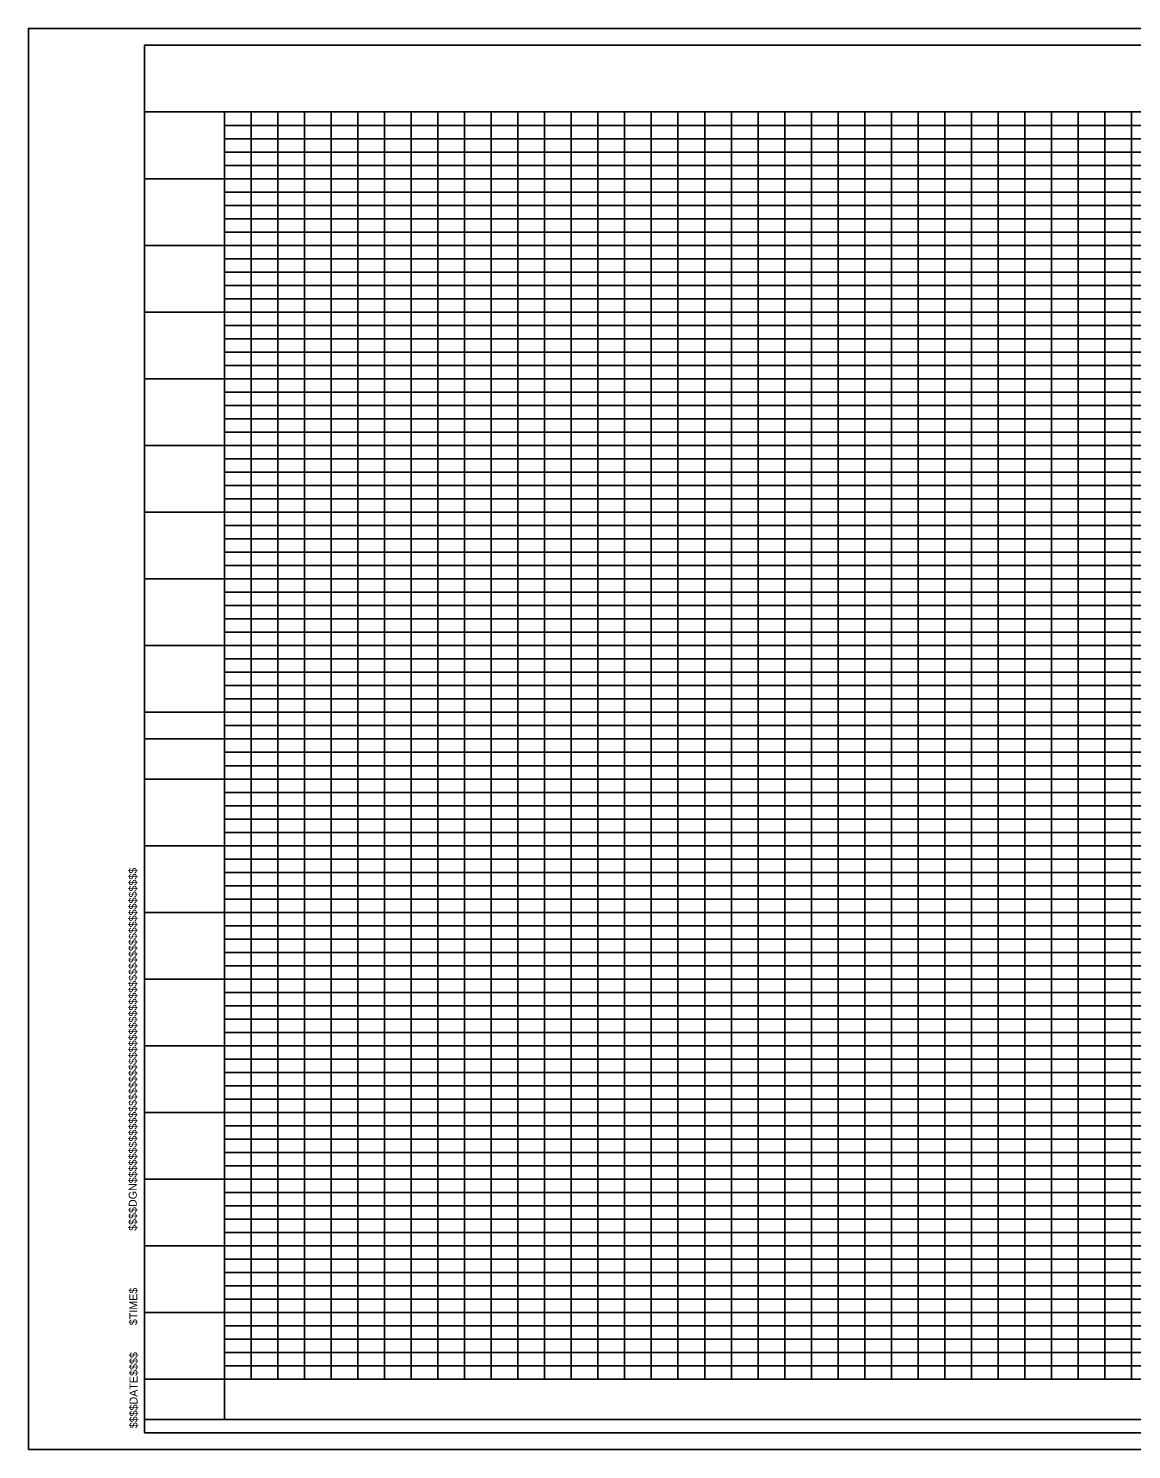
# Model space of a CAD drawing. Extents: x -87 to 2484, y -13 to 1056.
# Drawn here: x -87 to 740, y -13 to 1053 of the extents above; entities that cross this region are included whole.
import ezdxf

# ---------------------------------------------------------------- set-up
doc = ezdxf.new("R2010")
doc.units = 0
for name, color, linetype in [('D_CFL_Clip_Boundary_1', 7, 'Continuous'), ('D_CFL_Clip_Boundary_2', 7, 'Continuous'), ('D_CFL_Sheet_Border_ PlotShape', 7, 'Continuous'), ('D_CFL_Sheet_Border_Base', 7, 'Continuous'), ('D_CFL_Sheet_Border_Plan_Plan', 7, 'Continuous'), ('D_CFL_Sheet_Border_PnP', 7, 'Continuous'), ('D_CFL_Sheet_Border_Profile', 7, 'Continuous')]:
    doc.layers.add(name, color=color, linetype=linetype)

msp = doc.modelspace()

# ---------------------------------------------------------------- linework, layer by layer
at = {"layer": 'D_CFL_Clip_Boundary_1'}
msp.add_lwpolyline([(0, 520), (0, 1040), (1305, 1040), (1305, 1000), (1560, 1000), (1560, 520)], close=True, dxfattribs=at)
msp.add_lwpolyline([(0, 520), (0, 1040), (1305, 1040), (1305, 1000), (1560, 1000), (1560, 520)], close=True, dxfattribs=at)
at = {"layer": 'D_CFL_Clip_Boundary_2'}
msp.add_lwpolyline([(1500, 520), (60, 520), (60, 40), (1500, 40)], close=True, dxfattribs=at)
msp.add_lwpolyline([(1500, 520), (60, 520), (60, 40), (1500, 40)], close=True, dxfattribs=at)
at = {"layer": 'D_CFL_Sheet_Border_ PlotShape'}
msp.add_line((-86.9, -12.7), (-86.9, -12.7), dxfattribs=at)
msp.add_line((-86.9, -12.7), (-86.9, -12.7), dxfattribs=at)
msp.add_lwpolyline([(-86.9, -12.7), (1576.9, -12.7), (1576.9, 1052.6), (-86.9, 1052.6)], close=True, dxfattribs=at)
msp.add_lwpolyline([(-86.9, -12.7), (1576.9, -12.7), (1576.9, 1052.6), (-86.9, 1052.6)], close=True, dxfattribs=at)
at = {"layer": 'D_CFL_Sheet_Border_Base'}
msp.add_lwpolyline([(0, 0), (1560, 0), (1560, 1040), (0, 1040)], close=True, dxfattribs=at)
msp.add_lwpolyline([(0, 0), (1560, 0), (1560, 1040), (0, 1040)], close=True, dxfattribs=at)
at = {"layer": 'D_CFL_Sheet_Border_Plan_Plan'}
msp.add_line((0, 520), (1560, 520), dxfattribs=at)
msp.add_line((0, 520), (1560, 520), dxfattribs=at)
at = {"layer": 'D_CFL_Sheet_Border_PnP'}
for p, q in [((0, 520), (1560, 520)), ((0, 520), (1560, 520)), ((60, 520), (60, 10)), ((60, 520), (60, 10)), ((80, 40), (80, 520)), ((80, 40), (80, 520)), ((100, 40), (100, 520)), ((100, 40), (100, 520)), ((120, 40), (120, 520)), ((120, 40), (120, 520)), ((140, 40), (140, 520)), ((140, 40), (140, 520)), ((160, 40), (160, 520)), ((160, 40), (160, 520)), ((180, 40), (180, 520)), ((180, 40), (180, 520)), ((200, 39.7), (200, 519.7)), ((200, 39.7), (200, 519.7)), ((220, 39.7), (220, 519.7)), ((220, 39.7), (220, 519.7)), ((240, 39.7), (240, 519.7)), ((240, 39.7), (240, 519.7)), ((260, 39.7), (260, 519.7)), ((260, 39.7), (260, 519.7)), ((280, 40), (280, 520)), ((280, 40), (280, 520)), ((300, 39.7), (300, 519.7)), ((300, 39.7), (300, 519.7)), ((320, 39.7), (320, 519.7)), ((320, 39.7), (320, 519.7)), ((340, 39.7), (340, 519.7)), ((340, 39.7), (340, 519.7)), ((360, 39.7), (360, 519.7)), ((360, 39.7), (360, 519.7)), ((380, 40), (380, 520)), ((380, 40), (380, 520)), ((400, 39.7), (400, 519.7)), ((400, 39.7), (400, 519.7)), ((420, 39.7), (420, 519.7)), ((420, 39.7), (420, 519.7)), ((440, 39.7), (440, 519.7)), ((440, 39.7), (440, 519.7)), ((460, 39.7), (460, 519.7)), ((460, 39.7), (460, 519.7)), ((480, 40), (480, 520)), ((480, 40), (480, 520)), ((500, 39.7), (500, 519.7)), ((500, 39.7), (500, 519.7)), ((520, 39.7), (520, 519.7)), ((520, 39.7), (520, 519.7)), ((540, 39.7), (540, 519.7)), ((540, 39.7), (540, 519.7)), ((560, 39.7), (560, 519.7)), ((560, 39.7), (560, 519.7)), ((580, 40), (580, 520)), ((580, 40), (580, 520)), ((600, 39.7), (600, 519.7)), ((600, 39.7), (600, 519.7)), ((620, 39.7), (620, 519.7)), ((620, 39.7), (620, 519.7)), ((640, 39.7), (640, 519.7)), ((640, 39.7), (640, 519.7)), ((660, 39.7), (660, 519.7)), ((660, 39.7), (660, 519.7)), ((680, 40), (680, 520)), ((680, 40), (680, 520)), ((700, 39.7), (700, 519.7)), ((700, 39.7), (700, 519.7)), ((720, 39.7), (720, 519.7)), ((720, 39.7), (720, 519.7)), ((60, 510), (1500, 510)), ((60, 510), (1500, 510)), ((60, 500), (1500, 500)), ((60, 500), (1500, 500)), ((60, 490), (0, 490)), ((60, 490), (0, 490)), ((60, 490), (1500, 490)), ((60, 490), (1500, 490)), ((60, 480), (1500, 480)), ((60, 480), (1500, 480)), ((60, 470), (1500, 470)), ((60, 470), (1500, 470)), ((60, 460), (1500, 460)), ((60, 460), (1500, 460)), ((60, 450), (1500, 450)), ((60, 450), (1500, 450)), ((60, 440), (0, 440)), ((60, 440), (0, 440)), ((60, 440), (1500, 440)), ((60, 440), (1500, 440)), ((60, 430), (1500, 430)), ((60, 430), (1500, 430)), ((60, 420), (1500, 420)), ((60, 420), (1500, 420)), ((60, 410), (1500, 410)), ((60, 410), (1500, 410)), ((60, 400), (1500, 400)), ((60, 400), (1500, 400)), ((60, 390), (0, 390)), ((60, 390), (0, 390)), ((60, 390), (1500, 390)), ((60, 390), (1500, 390)), ((60, 380), (1500, 380)), ((60, 380), (1500, 380)), ((60, 370), (1500, 370)), ((60, 370), (1500, 370)), ((60, 360), (1500, 360)), ((60, 360), (1500, 360)), ((60, 350), (1500, 350)), ((60, 350), (1500, 350)), ((60, 340), (0, 340)), ((60, 340), (0, 340)), ((60, 340), (1500, 340)), ((60, 340), (1500, 340)), ((60, 330), (1500, 330)), ((60, 330), (1500, 330)), ((60, 320), (1500, 320)), ((60, 320), (1500, 320)), ((60, 310), (1500, 310)), ((60, 310), (1500, 310)), ((60, 300), (1500, 300)), ((60, 300), (1500, 300)), ((60, 290), (0, 290)), ((60, 290), (0, 290)), ((60, 290), (1500, 290)), ((60, 290), (1500, 290)), ((60, 280), (1500, 280)), ((60, 280), (1500, 280)), ((60, 270), (1500, 270)), ((60, 270), (1500, 270)), ((60, 260), (1500, 260)), ((60, 260), (1500, 260)), ((60, 250), (1500, 250)), ((60, 250), (1500, 250)), ((60, 240), (0, 240)), ((60, 240), (0, 240)), ((60, 240), (1500, 240)), ((60, 240), (1500, 240)), ((60, 230), (1500, 230)), ((60, 230), (1500, 230)), ((60, 220), (1500, 220)), ((60, 220), (1500, 220)), ((60, 210), (1500, 210)), ((60, 210), (1500, 210)), ((60, 200), (1500, 200)), ((60, 200), (1500, 200)), ((60, 190), (0, 190)), ((60, 190), (0, 190)), ((60, 190), (1500, 190)), ((60, 190), (1500, 190)), ((60, 180), (1500, 180)), ((60, 180), (1500, 180)), ((60, 170), (1500, 170)), ((60, 170), (1500, 170)), ((60, 160), (1500, 160)), ((60, 160), (1500, 160)), ((60, 150), (1500, 150)), ((60, 150), (1500, 150)), ((60, 140), (0, 140)), ((60, 140), (0, 140)), ((60, 140), (1500, 140)), ((60, 140), (1500, 140)), ((60, 130), (1500, 130)), ((60, 130), (1500, 130)), ((60, 120), (1500, 120)), ((60, 120), (1500, 120)), ((60, 110), (1500, 110)), ((60, 110), (1500, 110)), ((60, 100), (1500, 100)), ((60, 100), (1500, 100)), ((60, 90), (0, 90)), ((60, 90), (0, 90)), ((60, 90), (1500, 90)), ((60, 90), (1500, 90)), ((60, 80), (1500, 80)), ((60, 80), (1500, 80)), ((60, 70), (1500, 70)), ((60, 70), (1500, 70)), ((60, 60), (1500, 60)), ((60, 60), (1500, 60)), ((60, 50), (1500, 50)), ((60, 50), (1500, 50)), ((60, 40), (0, 40)), ((60, 40), (0, 40)), ((60, 40), (1500, 40)), ((60, 40), (1500, 40)), ((0, 10), (1560, 10)), ((0, 10), (1560, 10))]:
    msp.add_line(p, q, dxfattribs=at)
at = {"layer": 'D_CFL_Sheet_Border_Profile'}
for p, q in [((0, 990), (1560, 990)), ((0, 990), (1560, 990)), ((60, 990), (60, 10)), ((60, 990), (60, 10)), ((80, 40), (80, 990)), ((80, 40), (80, 990)), ((100, 40), (100, 990)), ((100, 40), (100, 990)), ((120, 40), (120, 990)), ((120, 40), (120, 990)), ((140, 40), (140, 990)), ((140, 40), (140, 990)), ((160, 40), (160, 990)), ((160, 40), (160, 990)), ((180, 40), (180, 990)), ((180, 40), (180, 990)), ((200, 40), (200, 990)), ((200, 40), (200, 990)), ((220, 40), (220, 990)), ((220, 40), (220, 990)), ((240, 40), (240, 990)), ((240, 40), (240, 990)), ((260, 40), (260, 990)), ((260, 40), (260, 990)), ((280, 40), (280, 990)), ((280, 40), (280, 990)), ((300, 40), (300, 990)), ((300, 40), (300, 990)), ((320, 40), (320, 990)), ((320, 40), (320, 990)), ((340, 40), (340, 990)), ((340, 40), (340, 990)), ((360, 40), (360, 990)), ((360, 40), (360, 990)), ((380, 40), (380, 990)), ((380, 40), (380, 990)), ((400, 40), (400, 990)), ((400, 40), (400, 990)), ((420, 40), (420, 990)), ((420, 40), (420, 990)), ((440, 40), (440, 990)), ((440, 40), (440, 990)), ((460, 40), (460, 990)), ((460, 40), (460, 990)), ((480, 40), (480, 990)), ((480, 40), (480, 990)), ((500, 40), (500, 990)), ((500, 40), (500, 990)), ((520, 40), (520, 990)), ((520, 40), (520, 990)), ((540, 40), (540, 990)), ((540, 40), (540, 990)), ((560, 40), (560, 990)), ((560, 40), (560, 990)), ((580, 40), (580, 990)), ((580, 40), (580, 990)), ((600, 40), (600, 990)), ((600, 40), (600, 990)), ((620, 40), (620, 990)), ((620, 40), (620, 990)), ((640, 40), (640, 990)), ((640, 40), (640, 990)), ((660, 40), (660, 990)), ((660, 40), (660, 990)), ((680, 40), (680, 990)), ((680, 40), (680, 990)), ((700, 40), (700, 990)), ((700, 40), (700, 990)), ((720, 40), (720, 990)), ((720, 40), (720, 990)), ((740, 40), (740, 990)), ((740, 40), (740, 990)), ((60, 980), (1500, 980)), ((60, 980), (1500, 980)), ((60, 970), (1500, 970)), ((60, 970), (1500, 970)), ((60, 960), (1500, 960)), ((60, 960), (1500, 960)), ((60, 950), (1500, 950)), ((60, 950), (1500, 950)), ((60, 940), (0, 940)), ((60, 940), (0, 940)), ((60, 940), (1500, 940)), ((60, 940), (1500, 940)), ((60, 930), (1500, 930)), ((60, 930), (1500, 930)), ((60, 920), (1500, 920)), ((60, 920), (1500, 920)), ((60, 910), (1500, 910)), ((60, 910), (1500, 910)), ((60, 900), (1500, 900)), ((60, 900), (1500, 900)), ((60, 890), (0, 890)), ((60, 890), (0, 890)), ((60, 890), (1500, 890)), ((60, 890), (1500, 890)), ((60, 880), (1500, 880)), ((60, 880), (1500, 880)), ((60, 870), (1500, 870)), ((60, 870), (1500, 870)), ((60, 860), (1500, 860)), ((60, 860), (1500, 860)), ((60, 850), (1500, 850)), ((60, 850), (1500, 850)), ((60, 840), (0, 840)), ((60, 840), (0, 840)), ((60, 840), (1500, 840)), ((60, 840), (1500, 840)), ((60, 830), (1500, 830)), ((60, 830), (1500, 830)), ((60, 820), (1500, 820)), ((60, 820), (1500, 820)), ((60, 810), (1500, 810)), ((60, 810), (1500, 810)), ((60, 800), (1500, 800)), ((60, 800), (1500, 800)), ((60, 790), (0, 790)), ((60, 790), (0, 790)), ((60, 790), (1500, 790)), ((60, 790), (1500, 790)), ((60, 780), (1500, 780)), ((60, 780), (1500, 780)), ((60, 770), (1500, 770)), ((60, 770), (1500, 770)), ((60, 760), (1500, 760)), ((60, 760), (1500, 760)), ((60, 750), (1500, 750)), ((60, 750), (1500, 750)), ((60, 740), (0, 740)), ((60, 740), (0, 740)), ((60, 740), (1500, 740)), ((60, 740), (1500, 740)), ((60, 730), (1500, 730)), ((60, 730), (1500, 730)), ((60, 720), (1500, 720)), ((60, 720), (1500, 720)), ((60, 710), (1500, 710)), ((60, 710), (1500, 710)), ((60, 700), (1500, 700)), ((60, 700), (1500, 700)), ((60, 690), (0, 690)), ((60, 690), (0, 690)), ((60, 690), (1500, 690)), ((60, 690), (1500, 690)), ((60, 680), (1500, 680)), ((60, 680), (1500, 680)), ((60, 670), (1500, 670)), ((60, 670), (1500, 670)), ((60, 660), (1500, 660)), ((60, 660), (1500, 660)), ((60, 650), (1500, 650)), ((60, 650), (1500, 650)), ((60, 640), (0, 640)), ((60, 640), (0, 640)), ((60, 640), (1500, 640)), ((60, 640), (1500, 640)), ((60, 630), (1500, 630)), ((60, 630), (1500, 630)), ((60, 620), (1500, 620)), ((60, 620), (1500, 620)), ((60, 610), (1500, 610)), ((60, 610), (1500, 610)), ((60, 600), (1500, 600)), ((60, 600), (1500, 600)), ((60, 590), (0, 590)), ((60, 590), (0, 590)), ((60, 590), (1500, 590)), ((60, 590), (1500, 590)), ((60, 580), (1500, 580)), ((60, 580), (1500, 580)), ((60, 570), (1500, 570)), ((60, 570), (1500, 570)), ((60, 560), (1500, 560)), ((60, 560), (1500, 560)), ((60, 550), (1500, 550)), ((60, 550), (1500, 550)), ((60, 540), (0, 540)), ((60, 540), (0, 540)), ((60, 540), (1500, 540)), ((60, 540), (1500, 540)), ((60, 530), (1500, 530)), ((60, 530), (1500, 530)), ((60, 520), (1500, 520)), ((60, 520), (1500, 520)), ((60, 510), (1500, 510)), ((60, 510), (1500, 510)), ((60, 500), (1500, 500)), ((60, 500), (1500, 500)), ((60, 490), (0, 490)), ((60, 490), (0, 490)), ((60, 490), (1500, 490)), ((60, 490), (1500, 490)), ((60, 480), (1500, 480)), ((60, 480), (1500, 480)), ((60, 470), (1500, 470)), ((60, 470), (1500, 470)), ((60, 460), (1500, 460)), ((60, 460), (1500, 460)), ((60, 450), (1500, 450)), ((60, 450), (1500, 450)), ((60, 440), (0, 440)), ((60, 440), (0, 440)), ((60, 440), (1500, 440)), ((60, 440), (1500, 440)), ((60, 430), (1500, 430)), ((60, 430), (1500, 430)), ((60, 420), (1500, 420)), ((60, 420), (1500, 420)), ((60, 410), (1500, 410)), ((60, 410), (1500, 410)), ((60, 400), (1500, 400)), ((60, 400), (1500, 400)), ((60, 390), (0, 390)), ((60, 390), (0, 390)), ((60, 390), (1500, 390)), ((60, 390), (1500, 390)), ((60, 380), (1500, 380)), ((60, 380), (1500, 380)), ((60, 370), (1500, 370)), ((60, 370), (1500, 370)), ((60, 360), (1500, 360)), ((60, 360), (1500, 360)), ((60, 350), (1500, 350)), ((60, 350), (1500, 350)), ((60, 340), (0, 340)), ((60, 340), (0, 340)), ((60, 340), (1500, 340)), ((60, 340), (1500, 340)), ((60, 330), (1500, 330)), ((60, 330), (1500, 330)), ((60, 320), (1500, 320)), ((60, 320), (1500, 320)), ((60, 310), (1500, 310)), ((60, 310), (1500, 310)), ((60, 300), (1500, 300)), ((60, 300), (1500, 300)), ((60, 290), (0, 290)), ((60, 290), (0, 290)), ((60, 290), (1500, 290)), ((60, 290), (1500, 290)), ((60, 280), (1500, 280)), ((60, 280), (1500, 280)), ((60, 270), (1500, 270)), ((60, 270), (1500, 270)), ((60, 260), (1500, 260)), ((60, 260), (1500, 260)), ((60, 250), (1500, 250)), ((60, 250), (1500, 250)), ((60, 240), (0, 240)), ((60, 240), (0, 240)), ((60, 240), (1500, 240)), ((60, 240), (1500, 240)), ((60, 230), (1500, 230)), ((60, 230), (1500, 230)), ((60, 220), (1500, 220)), ((60, 220), (1500, 220)), ((60, 210), (1500, 210)), ((60, 210), (1500, 210)), ((60, 200), (1500, 200)), ((60, 200), (1500, 200)), ((60, 190), (0, 190)), ((60, 190), (0, 190)), ((60, 190), (1500, 190)), ((60, 190), (1500, 190)), ((60, 180), (1500, 180)), ((60, 180), (1500, 180)), ((60, 170), (1500, 170)), ((60, 170), (1500, 170)), ((60, 160), (1500, 160)), ((60, 160), (1500, 160)), ((60, 150), (1500, 150)), ((60, 150), (1500, 150)), ((60, 140), (0, 140)), ((60, 140), (0, 140)), ((60, 140), (1500, 140)), ((60, 140), (1500, 140)), ((60, 130), (1500, 130)), ((60, 130), (1500, 130)), ((60, 120), (1500, 120)), ((60, 120), (1500, 120)), ((60, 110), (1500, 110)), ((60, 110), (1500, 110)), ((60, 100), (1500, 100)), ((60, 100), (1500, 100)), ((60, 90), (0, 90)), ((60, 90), (0, 90)), ((60, 90), (1500, 90)), ((60, 90), (1500, 90)), ((60, 80), (1500, 80)), ((60, 80), (1500, 80)), ((60, 70), (1500, 70)), ((60, 70), (1500, 70)), ((60, 60), (1500, 60)), ((60, 60), (1500, 60)), ((60, 50), (1500, 50)), ((60, 50), (1500, 50)), ((60, 40), (0, 40)), ((60, 40), (0, 40)), ((60, 40), (1500, 40)), ((60, 40), (1500, 40)), ((0, 10), (1560, 10)), ((0, 10), (1560, 10))]:
    msp.add_line(p, q, dxfattribs=at)

# ---------------------------------------------------------------- texts
at = {"layer": 'D_CFL_Sheet_Border_Base'}
for s, p in [('$$$$DGN$$$$$$$$$$$$$$$$$$$$$$$$$$$$$$$$$$$$$$$$$$$$$$$$$$$$$', (-5.7, 151.3)), ('$$$$DGN$$$$$$$$$$$$$$$$$$$$$$$$$$$$$$$$$$$$$$$$$$$$$$$$$$$$$', (-5.7, 151.3)), ('$TIME$', (-5.3, 80.6)), ('$TIME$', (-5.3, 80.6)), ('$$$$DATE$$$$', (-5.1, 3.3)), ('$$$$DATE$$$$', (-5.1, 3.3))]:
    msp.add_text(s, height=6, rotation=90, dxfattribs=at).set_placement(p)

doc.saveas('drawing.dxf')
